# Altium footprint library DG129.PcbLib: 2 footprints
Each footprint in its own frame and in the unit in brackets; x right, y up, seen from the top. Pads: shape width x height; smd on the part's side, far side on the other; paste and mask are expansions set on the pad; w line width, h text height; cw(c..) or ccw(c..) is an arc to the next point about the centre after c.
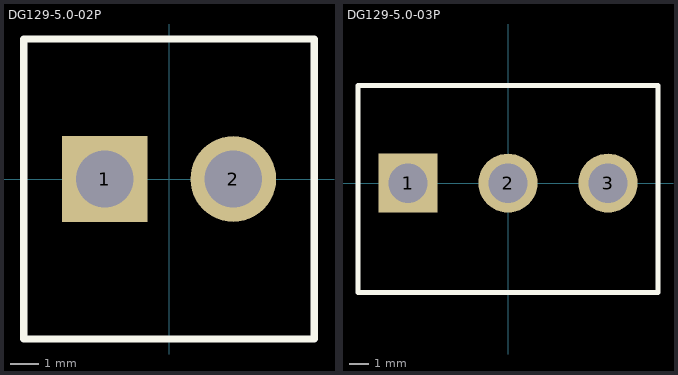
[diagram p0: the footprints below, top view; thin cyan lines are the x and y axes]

## DG129-5.0-02P [mm]
pads (2):
  rect 3x3 hole 2: 1(-2.25,0)
  round 3 hole 2: 2(2.25,0)
Top Overlay:
  lines w0.254: -5.08,-5.6 5.08,-5.6 5.08,4.9 -5.08,4.9 -5.08,-5.6
3D body "1776244-2--3DModel-STEP-1.STEP": height 10.08, standoff -3.42, extent -5.55,-4.05 5.61,3.45

## DG129-5.0-03P [mm]
pads (3):
  rect 3x3 hole 2: 1(-5.08,0)
  round 3 hole 2: 2(0,0) 3(5.08,0)
Top Overlay:
  lines w0.254: -7.62,-5.55 -7.62,4.95 7.62,4.95 7.62,-5.55 -7.62,-5.55
3D body "1776244-3--3DModel-STEP-1.STEP": height 10.08, standoff -3.42, extent -8.08,-4.05 8.08,3.45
